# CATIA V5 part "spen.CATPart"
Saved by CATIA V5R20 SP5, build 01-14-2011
Part number: Part1.1
Material "Road": density 7000 kg/m3
Bounding box of the stored display mesh (mm): x -2.75 to 2.75, y -1.5 to 1.5, z -1 to 95
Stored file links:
  E:\180212220\创新作业180212220\spen.CATPart
  C:\Program Files\Dassault Systemes\B20\intel_a\startup\materials\Catalog.CATMaterial
  C:\Program Files\Dassault Systemes\B20\intel_a\startup\materials\black_env_512x512.jpg
  C:\Program Files\Dassault Systemes\B20\intel_a\startup\materials\black_leather.jpg
  C:\Program Files\Dassault Systemes\B20\intel_a\startup\materials\wire.png
  C:\Program Files\Dassault Systemes\B20\intel_a\startup\materials\road.jpg
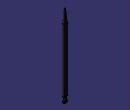
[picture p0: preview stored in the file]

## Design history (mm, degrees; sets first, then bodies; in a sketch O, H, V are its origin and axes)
Body1 (main body), material "Road"
  Sketch1 on xy-plane, origin (0, 0, 0), H (1, 0, 0), V (0, 1, 0)
    construction line L1 (-1.25, 0) -> (1.25, 0)
    point P1 (-1.25, 0)
    point P2 (1.25, 0)
    line L2 (-1.25, 1.5) -> (1.25, 1.5)
    line L3 (1.25, -1.5) -> (-1.25, -1.5)
    arc A1 centre (1.25, 0) radius 1.5 from (1.25, 1.5) to (1.25, -1.5) cw
    arc A2 centre (-1.25, 0) radius 1.5 from (-1.25, -1.5) to (-1.25, 1.5) cw
    distance L1 L2 = 1.5
    length L1 = 2.5
    distance P2 O = 1.25
    coincidence: P1 H
    horizontal: L1 H
    tangency: A1 L2, A2 L2, A1 L3, A2 L3
  Plane1: type Offset, RefPlane xy-plane, Offset 5
  Sketch2 on xy-plane, origin (0, 0, 0), H (1, 0, 0), V (0, 1, 0)
    line L1 (1, 1) -> (1, -1)
    line L2 (1, -1) -> (-1, -1)
    line L3 (-1, -1) -> (-1, 1)
    line L4 (-1, 1) -> (1, 1)
    length L1 = 2
    length L2 = 2
    vertical: L1 V, L3 V
    horizontal: L2 H, L4 H
    equidistance: L1 L3 O, L2 L4 O
  Pad1: profile Sketch2, direction (0, 0, 1), length 5
  Sketch3 on Plane1, origin (0, 0, 5), H (1, 0, 0), V (0, 1, 0)
    construction line L1 (-1.25, 0) -> (1.25, 0)
    point P1 (-1.25, 0)
    point P2 (1.25, 0)
    line L2 (-1.25, 1.5) -> (1.25, 1.5)
    line L3 (1.25, -1.5) -> (-1.25, -1.5)
    arc A1 centre (1.25, 0) radius 1.5 from (1.25, 1.5) to (1.25, -1.5) cw
    arc A2 centre (-1.25, 0) radius 1.5 from (-1.25, -1.5) to (-1.25, 1.5) cw
    distance L1 L2 = 1.5
    distance P2 O = 1.25
    length L1 = 2.5
    coincidence: P1 H
    horizontal: L1 H
    tangency: A1 L2, A2 L2, A1 L3, A2 L3
  Pad2: profile Sketch3, direction (0, 0, 1), length 75
  Pad3: profile Sketch1, direction (0, 0, -1), length 1
  Plane2: type Offset, RefPlane Plane1, Offset 75
  Plane3: type Offset, RefPlane Plane2, Offset 15
  Sketch4 on Plane3, origin (0, 0, 95), H (1, 0, 0), V (0, 1, 0)
    construction line L1 (-0.25, 0) -> (0.25, 0)
    point P1 (-0.25, 0)
    point P2 (0.25, 0)
    line L2 (-0.25, 0.3) -> (0.25, 0.3)
    line L3 (0.25, -0.3) -> (-0.25, -0.3)
    arc A1 centre (0.25, 0) radius 0.3 from (0.25, 0.3) to (0.25, -0.3) cw
    arc A2 centre (-0.25, 0) radius 0.3 from (-0.25, -0.3) to (-0.25, 0.3) cw
    distance L1 L2 = 0.3
    length L1 = 0.5
    distance O P2 = 0.25
    coincidence: P1 H
    horizontal: L1 H
    tangency: A1 L2, A2 L2, A1 L3, A2 L3
  Sketch5 on Plane2, origin (0, 0, 80), H (1, 0, 0), V (0, 1, 0)
    construction line L1 (-1.25, 0) -> (1.25, 0)
    point P2 (1.25, 0)
    line L2 (-1.25, 1.5) -> (1.25, 1.5)
    line L3 (1.25, -1.5) -> (-1.25, -1.5)
    arc A1 centre (1.25, 0) radius 1.5 from (1.25, 1.5) to (1.25, -1.5) cw
    arc A2 centre (-1.25, 0) radius 1.5 from (-1.25, -1.5) to (-1.25, 1.5) cw
    distance L1 L2 = 1.5
    length L1 = 2.5
    distance P2 O = 1.25
    horizontal: L1 H
    tangency: A1 L2, A2 L2, A1 L3, A2 L3
  Loft1: solid, Sections (Sketch4; Sketch5)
